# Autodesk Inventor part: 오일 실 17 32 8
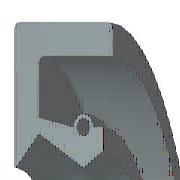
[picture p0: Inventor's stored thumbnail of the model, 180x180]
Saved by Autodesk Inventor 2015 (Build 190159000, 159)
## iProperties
IsCustomPart: 1
Created: 2012-02
Part Number: 오일 실 17 32 8
Material: 고무
Description: 오일-실
Document SubType Name: Modeling
Standard: KS B 2804
Designer: mduedu
Standards Organization: KS
Language: ko-KR
Size Designation: D - 17 32 8
Categories: <MemberInstance><Categories><Category DisplayName="샤프트 부품" InternalName="7f7aeb1f-a693-4053-b835-cee3144e0d98" Mnemonic="SHFT"><Category DisplayName="실링" Intern
Density: 0.93 g/cm^3
Appearance: 고무 - 검은색 - 버전 1.1
Mass: 2.28027 g
Surface Area: 32.1224 cm^2
Volume: 2.45191 cm^3
Author: mduedu
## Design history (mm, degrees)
revolve "본체" stored, may be unused: angle "d17" = 90 deg
revolve "스프링1" stored, may be unused: angle "d18" = 90 deg
body "Solid1"
sketch "스케치1"
  geometry: L1 (0, 16)-(8, 16); L2 (8, 14.25)-(1.75, 14.25); L3 (1.75, 10.25)-(4.9, 8.5); L4 (4.9, 8.5)-(0, 8.5); L5 (0, 0)-(9.586, 0) reference; L6 (4.9, 8.5)-(6.3, 9.375); L7 (0, 18)-(0, -3) reference; L8 (-1.941, 0)-(11.507, 0) reference; L9 (4.2, 10.6)-(1.75, 11.21); L10 (1.75, 11.21)-(1.75, 14.25); L11 (0, 16)-(0, 8.588); L12 (4.9, 8.5)-(0, 8.5); L13 (1.75, 10.25)-(0.152, 8.528); L14 (8, 16)-(8, 14.25); L15 (5.6, 10.6)-(6.3, 10.6); L16 (6.3, 10.6)-(6.3, 9.375); C1 r 0.455 at (4.9, 10.6); A1 r 0.7 centre (4.9, 10.6) between (5.6, 10.6) and (4.2, 10.6); A2 r 0.088 centre (0.088, 8.588) between (0, 8.588) and (0.152, 8.528); 1 further point
  constraints: 28 end point, 5 horizontal alignment, 5 point on line, 4 point on circle, 4 vertical alignment, 3 centre point, 3 tangent, 2 collinear, 2 horizontal, 2 perpendicular, 1 coincident, 1 parallel
  dimensions: "d0" = 32 diameter of L1 L5 (= SD2); "d1" = 1.75 distance of L1.end L2.start (= SD); "d2" = 0.91 diameter of C1 (= SPDI); "d3" = 1.4 diameter of A1 (= SPDA); "d4" = 17 diameter of L3.end L5 (= NND); "d5" = 20.5 diameter of L3.start L5 (= TKDM); "d7" = 22.42 diameter of L9.end L5 (= TKDM + 0.24 x SWDT); "d8" = 1.75 distance between parallel lines of L11 L10 (= SD); "d9" = 4.9 distance from line of L11 C1.centre (= SPDST); "d10" = 21.2 diameter of C1.centre L5 (= HLDM); "d11" = 0.0875 radius of A2 (= 0.25 x LAB); "d12" = 6.3 distance between parallel lines of L11 L16 (= SDI); "d13" = 18.75 diameter of L6.end L5 (= ABDM); "d14" = 8 distance from line of L11 L1.end (= SWDT)
fillet "모깎기1" dims "d6" = 0.3 (= RR)
other parameters: "SD2" = 32 [user parameter; used in 1 equation term], "SWDT" = 8 [user parameter; used in 2 equation terms], "RR" = 0.3 [user parameter; used in 1 equation term], "SD" = 1.75 [user parameter; used in 2 equation terms], "NND" = 17 [user parameter; used in 1 equation term], "SPDA" = 1.4 [user parameter; used in 1 equation term], "SPDI" = 0.91 [user parameter; used in 1 equation term], "TKDM" = 20.5 [user parameter; used in 2 equation terms], "HLDM" = 21.2 [user parameter; used in 1 equation term], "ABDM" = 18.75 [user parameter; used in 1 equation term], "SDI" = 6.3 [user parameter; used in 1 equation term], "SPDST" = 4.9 [user parameter; used in 1 equation term], "LAB" = 0.35 [user parameter; used in 1 equation term], "d15" = 0, "d16" = 0, "d19" = 0
